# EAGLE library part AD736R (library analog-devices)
ANALOG DEVICES
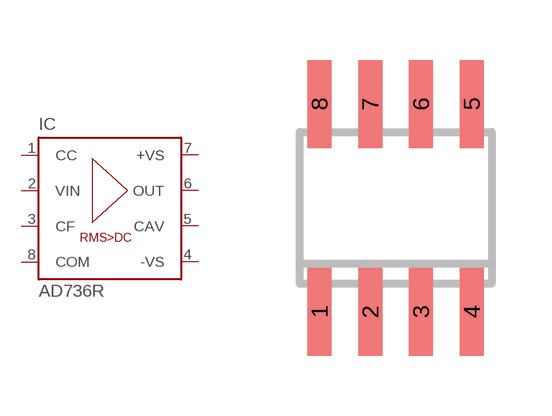
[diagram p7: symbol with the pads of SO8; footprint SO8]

Designator prefix IC

## AD736R (MPN: AD736JRZ; OC_FARNELL: 1701156; OC_NEWARK: 19M0863)  [SO8]
1  CC  pas
2  VIN  in
3  CF  pas
4  -VS  pwr
5  CAV  out
6  OUT  out
7  +VS  pwr
8  COM  pwr

## Footprint SO8 (pad centres in mm)
8-Lead Small Outline IC (SO-8) Source: http://www.analog.com/UploadedFiles/Data_Sheets/703465986AD8611_2_0.pdf
smd 0.6 x 2.2: 1 -1.905,-2.6; 2 -0.635,-2.6; 3 0.635,-2.6; 4 1.905,-2.6; 5 1.905,2.6; 6 0.635,2.6; 7 -0.635,2.6; 8 -1.905,2.6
